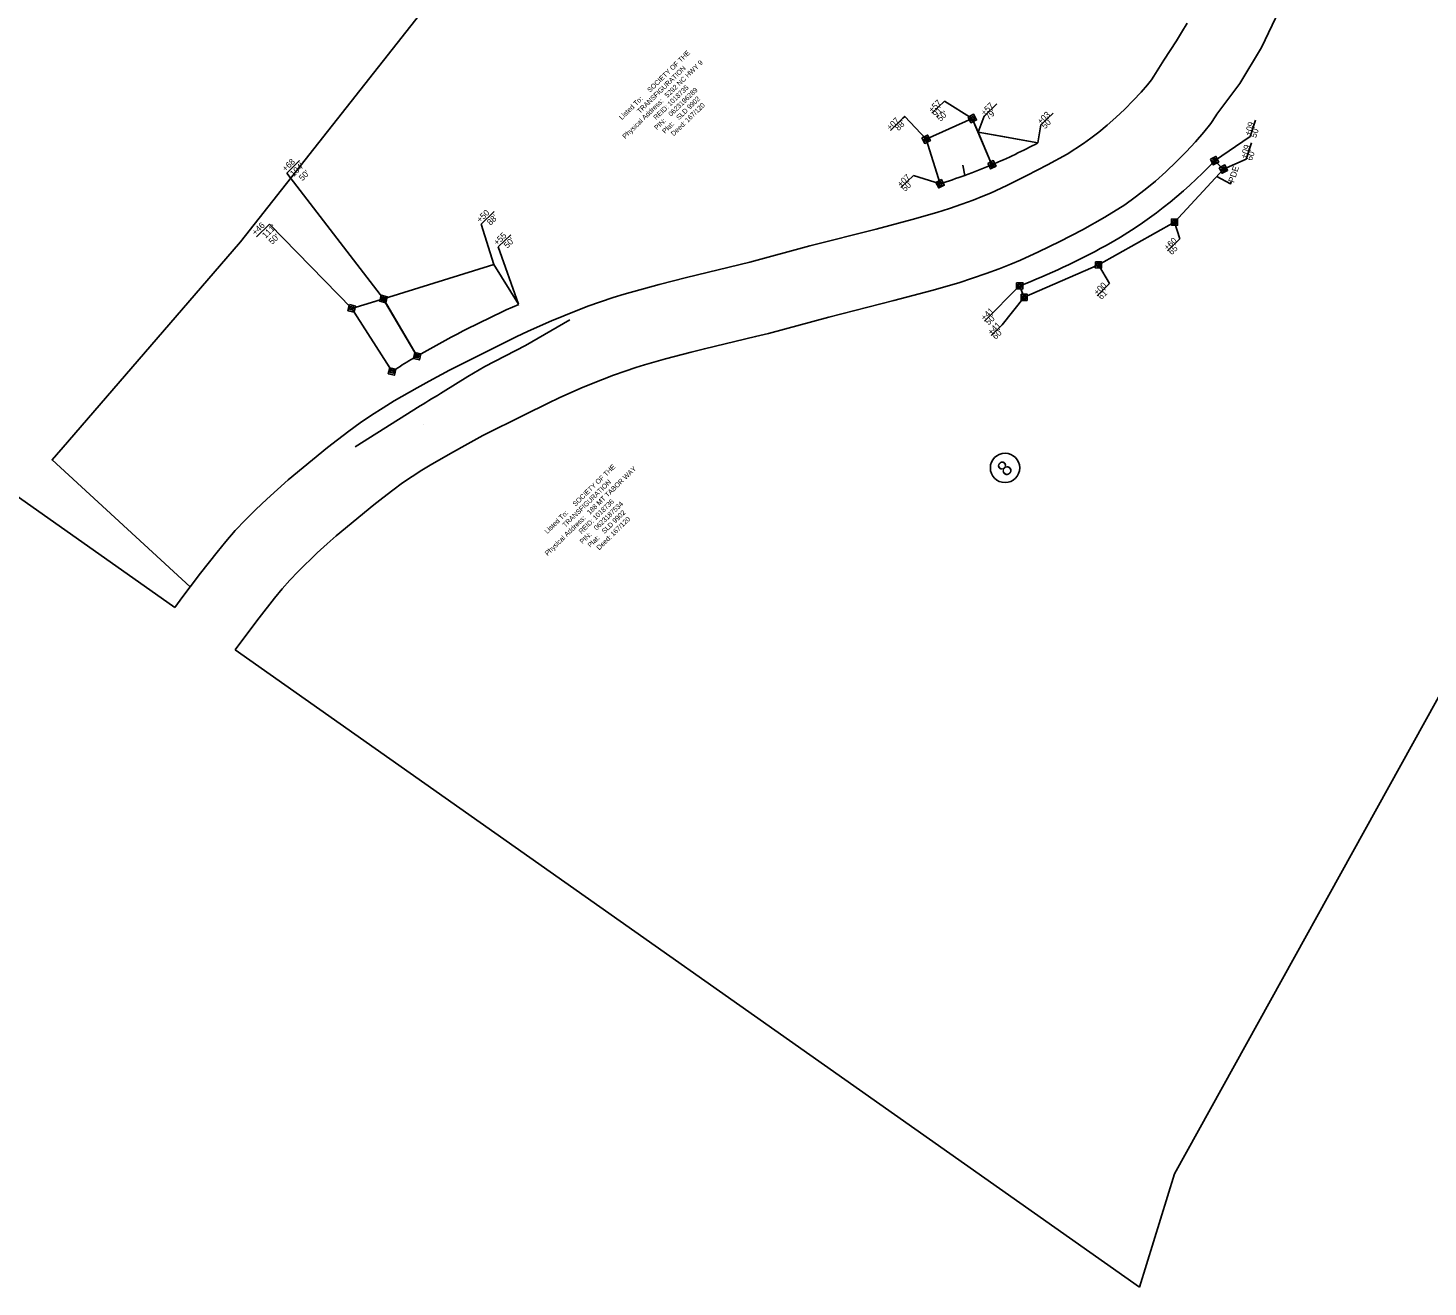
# Model space of a CAD drawing. Extents: x 1019969 to 1024963, y 638146 to 643978.
# Drawn here: x 1021029 to 1022170, y 638146 to 639172 of the extents above; entities that cross this region are included whole.
import ezdxf

# ---------------------------------------------------------------- set-up
doc = ezdxf.new("R2010")
doc.units = 0
for name, color, linetype in [('Old_Level_30', 7, 'Continuous'), ('Pattern 2', 7, 'Continuous'), ('Pattern 5', 7, 'Continuous'), ('Pattern 6', 7, 'Continuous'), ('Prop Easement Construction', 7, 'Continuous'), ('Prop Easement Construction Station Offsets', 7, 'Continuous'), ('Prop Easement Permanent Drainage', 7, 'Continuous'), ('Prop Easement Permanent Drainage Station Offsets', 7, 'Continuous'), ('Prop Parcel Number CELL', 7, 'Continuous'), ('Prop Parcel Owner Text', 7, 'Continuous'), ('Prop ROW Marker CELL', 7, 'Continuous'), ('Prop ROW Permanent Easement CELL', 7, 'Continuous'), ('Scratch_Level_1', 7, 'Continuous'), ('Scratch_Level_3', 7, 'Continuous')]:
    doc.layers.add(name, color=color, linetype=linetype)

msp = doc.modelspace()

# ---------------------------------------------------------------- linework, layer by layer
at = {"layer": 'Old_Level_30'}
for p, q in [((1020746.3, 638983.5), (1021148.4, 638700.1)), ((1021197.5, 638665.5), (1021934.4, 638146))]:
    msp.add_line(p, q, dxfattribs=at)
for points in [[(1021148.4, 638700.1), (1021154.9, 638708.9), (1021160.9, 638716.8), (1021048.3, 638820.3), (1021060.8, 638834.8), (1021201.8, 638998.1), (1021351.8, 639188.4), (1021478.2, 639259.2), (1021586.5, 639373.1), (1021590.2, 639390.9), (1021610.1, 639485.6), (1021596.2, 639589.1), (1021608.3, 639594.8), (1021691.4, 639633.5), (1021724, 639680.8), (1021857.3, 639719.7), (1021927.5, 639769), (1021938.4, 639784), (1022081, 639979.4), (1022077.7, 640018.6), (1022070.6, 640022.1), (1022064.2, 640025.1), (1021995.1, 640058.6)], [(1021973.2, 639176.4), (1021968.8, 639168.7), (1021964.6, 639161.9), (1021954.4, 639146.1), (1021946.2, 639133.1), (1021944.2, 639130.2), (1021940.9, 639126.1), (1021935.7, 639120.1), (1021929.3, 639113.2), (1021922.6, 639106.4), (1021915.1, 639099.4), (1021908.1, 639093.1), (1021901.4, 639087.6), (1021894.9, 639082.5), (1021888.9, 639078.2), (1021875.4, 639069.7), (1021859.6, 639060.9), (1021842.6, 639052.1), (1021826.3, 639044.1), (1021813.1, 639037.9), (1021806.8, 639035.3), (1021799, 639032.2), (1021789.6, 639028.8), (1021779.5, 639025.4), (1021769.4, 639022.1), (1021749.1, 639016.2), (1021719.8, 639008.5), (1021665.9, 638994.8), (1021617, 638981.6), (1021565.4, 638969.1), (1021543, 638963.3), (1021514.4, 638955.5), (1021505.5, 638952.8), (1021485, 638945.6), (1021465.3, 638937.9), (1021455.4, 638933.8), (1021436.3, 638925.2), (1021426.4, 638920.6), (1021372.1, 638893.6), (1021355.5, 638884.6), (1021345.9, 638879.2), (1021327.1, 638868.4), (1021318, 638862.9), (1021308.7, 638856.9), (1021299.4, 638850.6), (1021290.1, 638843.8), (1021280.8, 638836.7), (1021272.7, 638830.3), (1021240.8, 638804.2), (1021223.3, 638788.4), (1021214.3, 638779.8), (1021205.8, 638771.4), (1021197.6, 638762.7), (1021190, 638753.9), (1021182.8, 638745.2), (1021169.3, 638727.9), (1021160.9, 638716.8), (1021048.3, 638820.3), (1021060.8, 638834.8), (1021201.8, 638998.1), (1021351.8, 639188.4)], [(1022048.4, 639186.6), (1022033.9, 639156.6), (1022016.1, 639127.3), (1021997.6, 639102.2), (1021996.7, 639100.7), (1021992.7, 639094.7), (1021987, 639087.6), (1021980.1, 639079.7), (1021972.4, 639071.6), (1021964.5, 639063.6), (1021955.8, 639055.3), (1021947.4, 639047.7), (1021939.1, 639040.8), (1021930.8, 639034.4), (1021922.4, 639028.4), (1021906.1, 639018.1), (1021888, 639008), (1021869.5, 638998.4), (1021852.2, 638990), (1021837.6, 638983.2), (1021829.6, 638979.8), (1021820.1, 638976), (1021809.4, 638972.2), (1021798.3, 638968.4), (1021787.1, 638964.8), (1021765.3, 638958.4), (1021754.8, 638955.6), (1021734.3, 638950.3), (1021681.2, 638936.8), (1021632, 638923.5), (1021621.6, 638920.9), (1021579.9, 638910.9), (1021569.1, 638908.1), (1021561.9, 638906.2), (1021548.1, 638902.6), (1021531.1, 638897.9), (1021523.9, 638895.7), (1021515.3, 638892.7), (1021505.9, 638889.3), (1021487.8, 638882.3), (1021479.1, 638878.7), (1021461.6, 638870.9), (1021452.6, 638866.6), (1021433.4, 638857.1), (1021399.4, 638840.1), (1021384.6, 638832.1), (1021375.4, 638827), (1021357.7, 638816.8), (1021349.7, 638811.9), (1021341.8, 638806.9), (1021333.9, 638801.5), (1021325.9, 638795.7), (1021317.7, 638789.4), (1021310.4, 638783.6), (1021279.8, 638758.5), (1021272.4, 638752), (1021264.3, 638744.6), (1021248.8, 638729.4), (1021242.1, 638722.4), (1021235.8, 638715.1), (1021229.5, 638707.6), (1021217, 638691.5), (1021202.9, 638672.9), (1021197.5, 638665.5)], [(1021934.4, 638146), (1021963.1, 638238.4), (1022186.6, 638642.1)]]:
    msp.add_lwpolyline(points, dxfattribs=at)
at = {"layer": 'Pattern 2'}
for p, q in [((1021798.2, 639098.6), (1021760.7, 639081.7)), ((1021802.9, 639087.6), (1021798.2, 639098.6)), ((1021760.7, 639081.7), (1021771.9, 639045.4)), ((1021814.2, 639060.9), (1021802.9, 639087.6)), ((1021792.1, 639052.2), (1021790.6, 639060.6)), ((1021790.6, 639060.6), (1021792.1, 639052.2)), ((1021963, 639014.2), (1022002.9, 639057.4)), ((1022002.9, 639057.4), (1021995.6, 639064.2)), ((1021901, 638979.3), (1021963, 639014.2)), ((1021840.4, 638952.9), (1021901, 638979.3)), ((1021836.8, 638962.2), (1021840.4, 638952.9)), ((1021315.6, 638950.7), (1021292.5, 638943.8)), ((1021292.5, 638943.8), (1021294.4, 638940.8)), ((1021344, 638908), (1021320.1, 638948.5)), ((1021323.5, 638895.5), (1021325.4, 638892.5)), ((1021325.4, 638892.5), (1021328.4, 638894.4))]:
    msp.add_line(p, q, dxfattribs=at)
for points in [[(1021294.4, 638940.8), (1021294.4, 638940.8), (1021323.5, 638895.5)], [(1021320.1, 638948.5), (1021318.4, 638951.5), (1021315.6, 638950.7)], [(1021342.7, 638903.2), (1021345.7, 638905), (1021344, 638908)]]:
    msp.add_lwpolyline(points, dxfattribs=at)
for centre, radius, start, end in [((1021637.5, 639478.9), 453.8, 289.9268, 292.9183), ((1021728.7, 639314.9), 366.2, 299.0831, 316.8016), ((1021637.5, 639478.9), 453.8, 287.2324, 289.9268), ((1021637.5, 639478.9), 553.8, 291.0988, 299.0831), ((1021666.3, 638360.4), 631.9, 120.8046, 122.3281)]:
    msp.add_arc(centre, radius, start, end, dxfattribs=at)
at = {"layer": 'Pattern 6'}
for p, q in [((1021821.6, 639084.2), (1021802.9, 639087.6)), ((1021802.9, 639087.6), (1021807.4, 639076.9)), ((1021851.6, 639078.7), (1021821.6, 639084.2)), ((1021807.4, 639076.9), (1021814.2, 639060.9)), ((1021408.2, 638979.7), (1021318.4, 638951.5)), ((1021428.5, 638947.2), (1021408.2, 638979.7)), ((1021408.2, 638979.7), (1021408.2, 638979.7)), ((1021318.4, 638951.5), (1021345.7, 638905)), ((1021428.5, 638947.2), (1021428.5, 638947.2)), ((1021349.1, 638906.9), (1021349.1, 638906.9))]:
    msp.add_line(p, q, dxfattribs=at)
for centre, radius, start, end in [((1021637.5, 639478.9), 453.8, 292.9183, 298.1493), ((1021780.7, 638154), 867.8, 113.9416, 119.827), ((1021415.5, 638789.4), 135, 119.4989, 121.1265)]:
    msp.add_arc(centre, radius, start, end, dxfattribs=at)
at = {"layer": 'Prop Easement Construction'}
for p, q in [((1021802.9, 639087.6), (1021851.6, 639078.7)), ((1021318.4, 638951.5), (1021408.2, 638979.7)), ((1021408.2, 638979.7), (1021428.5, 638947.2))]:
    msp.add_line(p, q, dxfattribs=at)
at = {"layer": 'Prop Easement Construction Station Offsets'}
for p, q in [((1021818.2, 639110.6), (1021808, 639100.6)), ((1021864, 639103.1), (1021854, 639093.4)), ((1021408.5, 639022.7), (1021398, 639012.5)), ((1021422.1, 639003.9), (1021411.9, 638993.9))]:
    msp.add_line(p, q, dxfattribs=at)
for points in [[(1021808, 639100.6), (1021802.9, 639087.6)], [(1021854, 639093.4), (1021851.6, 639078.7)], [(1021398, 639012.5), (1021408.2, 638979.7)], [(1021411.9, 638993.9), (1021428.5, 638947.2)]]:
    msp.add_lwpolyline(points, dxfattribs=at)
at = {"layer": 'Prop Easement Permanent Drainage'}
for p, q in [((1021760.7, 639081.7), (1021798.2, 639098.6)), ((1021814.2, 639060.9), (1021798.2, 639098.6)), ((1021771.9, 639045.4), (1021760.7, 639081.7)), ((1021963, 639014.2), (1022002.9, 639057.4)), ((1021995.6, 639064.2), (1022002.9, 639057.4)), ((1021901, 638979.3), (1021963, 639014.2)), ((1021840.5, 638952.9), (1021901, 638979.3)), ((1021836.8, 638962.2), (1021840.4, 638952.9)), ((1021292.5, 638943.8), (1021318.4, 638951.5)), ((1021325.4, 638892.5), (1021292.5, 638943.8)), ((1021345.7, 638905), (1021318.4, 638951.5))]:
    msp.add_line(p, q, dxfattribs=at)
at = {"layer": 'Prop Easement Permanent Drainage Station Offsets'}
for p, q in [((1021775.5, 639112.9), (1021765.3, 639103)), ((1021741.7, 639098.8), (1021731.5, 639088.8)), ((1022028.9, 639097.4), (1022024.6, 639084.1)), ((1022025.6, 639078.8), (1022021.3, 639065.5)), ((1021250, 639064.4), (1021239.5, 639054.1)), ((1021750.2, 639052.2), (1021740, 639042.3)), ((1021225.5, 639012.5), (1021214.9, 639002.2)), ((1021967.3, 639000.6), (1021957.2, 638990.7)), ((1021910.1, 638964.1), (1021899.9, 638954.2)), ((1021816.9, 638942.1), (1021808.1, 638933.5)), ((1021822.6, 638930.4), (1021813.7, 638921.8))]:
    msp.add_line(p, q, dxfattribs=at)
for points in [[(1021775.5, 639112.9), (1021798.2, 639098.6)], [(1021741.7, 639098.8), (1021743.2, 639100.3), (1021760.7, 639081.7)], [(1022024.6, 639084.1), (1021995.6, 639064.2)], [(1022021.3, 639065.5), (1022002.9, 639057.4)], [(1021239.5, 639054.1), (1021318.4, 638951.5)], [(1021750.2, 639052.2), (1021771.9, 639045.4)], [(1022009.2, 639047.1), (1022008.7, 639045.4), (1021997.5, 639051.5)], [(1021225.5, 639012.5), (1021292.5, 638943.8)], [(1021967.3, 639000.6), (1021963, 639014.2)], [(1021910.1, 638964.1), (1021901, 638979.3)], [(1021808.1, 638933.5), (1021836.8, 638962.2)], [(1021822.6, 638930.4), (1021840.4, 638952.9)]]:
    msp.add_lwpolyline(points, dxfattribs=at)
at = {"layer": 'Prop Parcel Number CELL'}
msp.add_line((1021824.9, 638813.8), (1021824.9, 638813.8), dxfattribs=at)
msp.add_circle((1021824.9, 638813.8), 12, dxfattribs=at)
at = {"layer": 'Prop ROW Marker CELL'}
for p, q in [((1021798.2, 639098.6), (1021798.2, 639098.6)), ((1021760.7, 639081.7), (1021760.7, 639081.7)), ((1021814.2, 639060.9), (1021814.2, 639060.9)), ((1021995.6, 639064.2), (1021995.6, 639064.2)), ((1022002.9, 639057.4), (1022002.9, 639057.4)), ((1021771.9, 639045.4), (1021771.9, 639045.4)), ((1021963, 639014.2), (1021963, 639014.2)), ((1021901, 638979.3), (1021901, 638979.3)), ((1021836.8, 638962.2), (1021836.8, 638962.2)), ((1021840.4, 638952.9), (1021840.4, 638952.9)), ((1021292.5, 638943.8), (1021292.5, 638943.8)), ((1021318.4, 638951.5), (1021318.4, 638951.5)), ((1021345.7, 638905), (1021345.7, 638905)), ((1021325.4, 638892.5), (1021325.4, 638892.5))]:
    msp.add_line(p, q, dxfattribs=at)
at = {"layer": 'Prop ROW Permanent Easement CELL'}
for points in [[(1021794.8, 639099.8), (1021799.3, 639102.1), (1021801.7, 639097.5), (1021797.1, 639095.2)], [(1021796.5, 639099.2), (1021798.8, 639100.4), (1021799.9, 639098.1), (1021797.7, 639096.9)], [(1021757.2, 639082.8), (1021761.8, 639085.2), (1021764.1, 639080.6), (1021759.5, 639078.3)], [(1021758.9, 639082.3), (1021761.2, 639083.4), (1021762.4, 639081.2), (1021760.1, 639080)], [(1021992.2, 639065.4), (1021996.7, 639067.7), (1021999.1, 639063.1), (1021994.5, 639060.8)], [(1021993.9, 639064.8), (1021996.2, 639066), (1021997.3, 639063.7), (1021995.1, 639062.5)], [(1021810.8, 639062), (1021815.3, 639064.3), (1021817.6, 639059.8), (1021813.1, 639057.5)], [(1021812.5, 639061.4), (1021814.8, 639062.6), (1021815.9, 639060.3), (1021813.6, 639059.2)], [(1021999.5, 639058.5), (1022004, 639060.8), (1022006.3, 639056.3), (1022001.8, 639054)], [(1022001.2, 639058), (1022003.5, 639059.1), (1022004.6, 639056.8), (1022002.4, 639055.7)], [(1021768.5, 639046.5), (1021773, 639048.9), (1021775.3, 639044.3), (1021770.8, 639042)], [(1021770.2, 639046), (1021772.5, 639047.1), (1021773.6, 639044.9), (1021771.4, 639043.7)], [(1021960.4, 639016.8), (1021965.5, 639016.7), (1021965.5, 639011.6), (1021960.4, 639011.7)], [(1021961.7, 639015.5), (1021964.2, 639015.5), (1021964.2, 639012.9), (1021961.7, 639013)], [(1021898.5, 638981.9), (1021903.5, 638981.8), (1021903.5, 638976.7), (1021898.4, 638976.8)], [(1021899.7, 638980.6), (1021902.3, 638980.5), (1021902.2, 638978), (1021899.7, 638978)], [(1021834.3, 638964.8), (1021839.4, 638964.7), (1021839.3, 638959.6), (1021834.3, 638959.7)], [(1021835.6, 638963.5), (1021838.1, 638963.4), (1021838.1, 638960.9), (1021835.5, 638960.9)], [(1021316.4, 638954.5), (1021321.4, 638953.4), (1021320.3, 638948.4), (1021315.3, 638949.6)], [(1021317.4, 638953), (1021319.9, 638952.5), (1021319.3, 638950), (1021316.8, 638950.5)], [(1021837.9, 638955.4), (1021843, 638955.4), (1021842.9, 638950.3), (1021837.9, 638950.3)], [(1021839.2, 638954.1), (1021841.7, 638954.1), (1021841.7, 638951.6), (1021839.1, 638951.6)], [(1021290.6, 638946.9), (1021295.5, 638945.7), (1021294.4, 638940.8), (1021289.4, 638941.9)], [(1021291.5, 638945.3), (1021294, 638944.8), (1021293.4, 638942.3), (1021291, 638942.9)], [(1021343.8, 638908), (1021348.8, 638906.9), (1021347.7, 638901.9), (1021342.7, 638903)], [(1021344.8, 638906.5), (1021347.3, 638905.9), (1021346.7, 638903.4), (1021344.2, 638904)], [(1021323.5, 638895.5), (1021328.4, 638894.4), (1021327.3, 638889.4), (1021322.3, 638890.5)], [(1021324.4, 638894), (1021326.9, 638893.4), (1021326.4, 638890.9), (1021323.9, 638891.5)]]:
    msp.add_lwpolyline(points, close=True, dxfattribs=at)
at = {"layer": 'Scratch_Level_1'}
msp.add_line((1021350.7, 638849.3), (1021350.7, 638849.3), dxfattribs=at)
at = {"layer": 'Scratch_Level_3'}
msp.add_line((1021348.3, 638864.3), (1021295.3, 638830.9), dxfattribs=at)
msp.add_lwpolyline([(1021367.1, 638875.8), (1021387.1, 638888.2), (1021400.9, 638896.4), (1021434.1, 638913.7), (1021470.3, 638934.4)], dxfattribs=at)
msp.add_arc((1021666.3, 638360.4), 595.9, 120.1389, 122.2588, dxfattribs=at)

# ---------------------------------------------------------------- texts
at = {"layer": 'Pattern 5'}
for s, p in [('SOCIETY OF THE ', (1021535.6, 639119.6)), ('TRANSFIGURATION', (1021527.3, 639102.4)), ('5292 NC HWY 9', (1021549.8, 639115.3)), ('1018735', (1021552, 639108.4)), ('0623196289', (1021552.8, 639100)), ('Listed To:', (1021512.7, 639097.3)), ('Physical Address:', (1021515.4, 639081.8)), ('SLD 9902', (1021559.2, 639097.2)), ('REID:', (1021540.6, 639097.2)), ('167/120', (1021566.4, 639095.1)), ('PIN:', (1021541.3, 639088.9)), ('Plat:', (1021547.8, 639086.1)), ('Deed:', (1021554.9, 639084)), ('SOCIETY OF THE ', (1021474.8, 638782.1)), ('188 MT TABOR WAY', (1021486.5, 638775.4)), ('TRANSFIGURATION', (1021466.5, 638765)), ('1018736', (1021491.2, 638770.9)), ('0623187534', (1021492.1, 638762.6)), ('Listed To:', (1021451.9, 638759.8)), ('Physical Address:', (1021452.1, 638741.9)), ('REID:', (1021479.7, 638759.7)), ('SLD 9902', (1021498.4, 638759.8)), ('167/120', (1021505.6, 638757.7)), ('PIN:', (1021480.6, 638751.5)), ('Plat:', (1021487, 638748.6)), ('Deed:', (1021494.2, 638746.5))]:
    msp.add_text(s, height=4, rotation=44.2601, dxfattribs=at).set_placement(p)
at = {"layer": 'Prop Easement Construction Station Offsets'}
for s, p in [('+57', (1021808, 639100.7)), ("79'", (1021811.6, 639097)), ('+03', (1021854, 639093.4)), ("50'", (1021857.5, 639089.8)), ('+50', (1021397.1, 639013.4)), ("88'", (1021405.6, 639011.2)), ('+55', (1021411, 638994.8)), ("50'", (1021419.3, 638992.5))]:
    msp.add_text(s, height=5, rotation=44.2601, dxfattribs=at).set_placement(p)
at = {"layer": 'Prop Easement Permanent Drainage Station Offsets'}
for s, rotation, p in [('+57', 44.2601, (1021765.3, 639103)), ("91'", 44.2601, (1021768.8, 639099.4)), ("50'", 44.2601, (1021772.3, 639095.8)), ('+07', 44.2601, (1021731.2, 639088.5)), ("88'", 44.2601, (1021738.1, 639088.3)), ('+09', 71.9903, (1022024.6, 639084.1)), ("50'", 71.9903, (1022029.4, 639082.5)), ('+09', 71.9903, (1022021.3, 639065.5)), ("60'", 71.9903, (1022026.1, 639063.9)), ('+68', 44.2601, (1021238.6, 639055)), ("104'", 44.2601, (1021245.1, 639050.9)), ("50'", 44.2601, (1021252.3, 639047.4)), ('PDE', 71.9903, (1022011.4, 639045.9)), ('+07', 44.2601, (1021740, 639042.3)), ("50'", 44.2601, (1021743.5, 639038.7)), ('+46', 44.2601, (1021214, 639003.1)), ("111'", 44.2601, (1021222.3, 639000.6)), ("50'", 44.2601, (1021227.7, 638995.5)), ('+60', 44.2601, (1021957.2, 638990.7)), ("65'", 44.2601, (1021960.7, 638987.1)), ('+00', 44.2601, (1021899.9, 638954.2)), ("61'", 44.2601, (1021903.4, 638950.6)), ('+41', 44.2601, (1021808.1, 638933.5)), ("50'", 44.2601, (1021811.6, 638929.9)), ('+41', 44.2601, (1021813.7, 638921.8)), ("60'", 44.2601, (1021817.3, 638918.2))]:
    msp.add_text(s, height=5, rotation=rotation, dxfattribs=at).set_placement(p)
at = {"layer": 'Prop Parcel Owner Text'}
msp.add_text('8', height=12.2, rotation=44.2601, dxfattribs=at).set_placement((1021825.6, 638806))

doc.saveas('drawing.dxf')
